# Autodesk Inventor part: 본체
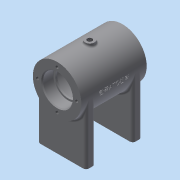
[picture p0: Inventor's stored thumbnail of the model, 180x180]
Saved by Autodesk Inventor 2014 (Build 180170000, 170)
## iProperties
Created: 2020-07
Part Number: 본체
Material: Generic
Document SubType Name: Modeling
Designer: kh
Density: 1 g/cm^3
Appearance: Default
Mass: 113.054 g
Surface Area: 357.567 cm^2
Volume: 113.054 cm^3
Author: kh
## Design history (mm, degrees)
sketch "Sketch1"
  geometry: C1 r 26 at (0, 0); 1 further point
  constraints: 1 centre point, 1 coincident
  dimensions: "d0" = 52 diameter of C1
extrude "Extrusion1" new body sketch "Sketch1" distance "d1" = 70; taper "d2" = 0 deg
workplane "Work Plane1"
sketch "Sketch2"
  geometry: L1 (-26, 0)-(26, 0); L2 (26, 0)-(26, -64); L3 (26, -64)-(-26, -64); L4 (-26, -64)-(-26, 0); 2 further points
  constraints: 8 end point, 2 coincident, 2 parallel, 1 horizontal, 1 midpoint, 1 perpendicular
  dimensions: "d4" = 64 distance from line of L3 point (0, 0); "d5" = 52 distance of L2.end L3.end
extrude "Extrusion2" join sketch "Sketch2" distance "d6" = 10; taper "d7" = 0 deg
workplane "Work Plane2"
mirror "Mirror1"
sketch "Sketch3"
  geometry: L1 (-26, 0)-(26, 0) reference; L2 (0, 70)-(0, 0); L3 (16, 70)-(16, 58); L4 (16, 58)-(14, 58); L5 (14, 58)-(14, 56); L6 (14, 56)-(21, 56); L7 (21, 56)-(21, 14); L8 (21, 14)-(14, 14); L9 (14, 14)-(14, 12); L10 (14, 12)-(16, 12); L11 (16, 12)-(16, 0); L12 (0, 0)-(16, 0); L13 (26, 70)-(-26, 70) reference; L14 (16, 70)-(0, 70); 2 further points
  constraints: 24 end point, 6 parallel, 3 perpendicular, 2 collinear, 2 midpoint, 1 horizontal alignment, 1 point on line
  dimensions: "d9" = 32 diameter of L3 L2; "d10" = 32 diameter of L11 L2; "d11" = 28 diameter of L5 L2; "d12" = 28 diameter of L9 L2; "d13" = 42 diameter of L7 L2; "d14" = 35 distance from line of point (21, 35) L13; "d15" = 12 distance of L3.start L3.end; "d16" = 12 distance of L10.end L11.end; "d17" = 2 distance of L4.end L5.end
revolve "Revolution1" sketch "Sketch3" stored, may be unused: angle "d18" = 90 deg
sketch "Sketch4"
  geometry: L1 (0, 0)-(0, -26); L2 (0, 0)-(-8.893, -24.432); L3 (0, 0)-(-24.195, 8.806); L4 (-9.919, -27.251)-(-33.512, -18.664); L5 (-9.919, -27.251)-(-4.28, -29.303); L6 (-4.28, -29.303)-(-3.014, -25.825); L7 (-8.893, -24.432)-(-9.919, -27.251); A1 r 26 centre (0, 0) between (-26, 0) and (26, 0) reference; A2 r 6 centre (-9.919, -27.251) between (-4.28, -29.303) and (-13.336, -22.319); A3 r 26 centre (0, 0) between (0, -26) and (-13.336, -22.319); A4 r 26 centre (0, 0) between (-8.893, -24.432) and (-3.014, -25.825); 4 further points
  constraints: 14 end point, 9 point on circle, 3 centre point, 3 coincident, 2 parallel, 2 perpendicular, 1 collinear, 1 point on line, 1 tangent
  dimensions: "d19" = 20 deg angle of L2 L1; "d21" = 29 distance between parallel lines of L4 L3; "d23" = 12 diameter of A2
revolve "Revolution2" sketch "Sketch4" stored, may be unused: angle "d24" = 90 deg
workplane "Work Plane3"
sketch "Sketch5"
  geometry: L1 (26, 70)-(-26, 70) reference; C1 r 5 at (0, 35); 1 further point
  constraints: 1 centre point
  dimensions: "d26" = 10 diameter of C1; "d27" = 35 distance from line of C1.centre L1
extrude "Extrusion3" join sketch "Sketch5" stored distance "d28" = 10; taper "d29" = 0 deg
hole "Hole1" diameter "d32" = 5.188; stored, may be unused: countersink angle "d36" = 90 deg, drill point angle "d38" = 118 deg; dims "d33" = 6, "d34" = 4, "d35" = 2, "d37" = 19.75, "d80" = 10, "d81" = 10
hole "Hole2" diameter "d41" = 5.188; stored, may be unused: countersink angle "d45" = 90 deg, drill point angle "d47" = 118 deg; dims "d42" = 6, "d43" = 4, "d44" = 2, "d46" = 19.75, "d82" = 10, "d83" = 10
sketch "Sketch6"
  geometry: C1 r 26 at (0, 0) reference; A1 r 21 centre (0, 0) between (0, 21) and (-21, 0); 2 further points
  constraints: 4 point on circle, 1 centre point, 1 coincident
  dimensions: "d48" = 42 diameter of A1
hole "Hole3" sketch "Sketch6" at (0, 21), (-21, 0), (21, 0), (0, -21) diameter "d49" = 3.242; stored, may be unused: countersink angle "d53" = 90 deg, drill point angle "d55" = 118 deg; dims "d50" = 8, "d51" = 4, "d52" = 2, "d54" = 10
mirror "Mirror2"
sketch "Sketch7"
  geometry: L1 (52, 0)-(0, 0) reference; L2 (52, 0)-(52, -10) reference; L3 (26, 0)-(26, -46.152); 3 further points
  constraints: 2 end point, 1 midpoint, 1 parallel
  dimensions: "d56" = 5 distance from line of point (46, -5) L1; "d57" = 5 distance from line of point (6, -5) L1; "d58" = 20 distance from line of point (46, -5) L3; "d59" = 20 distance from line of L3 point (6, -5)
hole "Hole4" sketch "Sketch7" at (46, -5), (6, -5) diameter "d60" = 4.134; stored, may be unused: countersink angle "d64" = 90 deg, drill point angle "d66" = 118 deg; dims "d61" = 8, "d62" = 4, "d63" = 2, "d65" = 10
mirror "Mirror3"
workplane "Work Plane4"
sketch "Sketch8"
  geometry: L1 (26, 70)-(-26, 70) reference; L2 (26, 0)-(26, 70) reference; 2 further points
  constraints: 1 other
  dimensions: "d68" = 35 distance from line of point (0, 35) L1; "d69" = 26 distance from line of L2 point (0, 35)
emboss "Emboss1" sketch "Sketch8" dims "d9" = 32, "d10" = 32, "d11" = 28, "d12" = 28, "d13" = 42, "d14" = 35, "d15" = 12, "d16" = 12, "d17" = 2, "d70" = 0.5, "d71" = 0
chamfer "Chamfer1" distance "d72" = 1; stored, may be unused: second distance "d73" = 2, angle "d74" = 45 deg
fillet "Fillet1" dims "d75" = 3
fillet "Fillet2" dims "d76" = 2
fillet "Fillet3" dims "d77" = 0.3, "d78" = 3
fillet "Fillet4" dims "d79" = 3
body "Solid1"
other parameters: "d3" = -5, "d8" = -35, "d25" = 29, "d67" = 26
